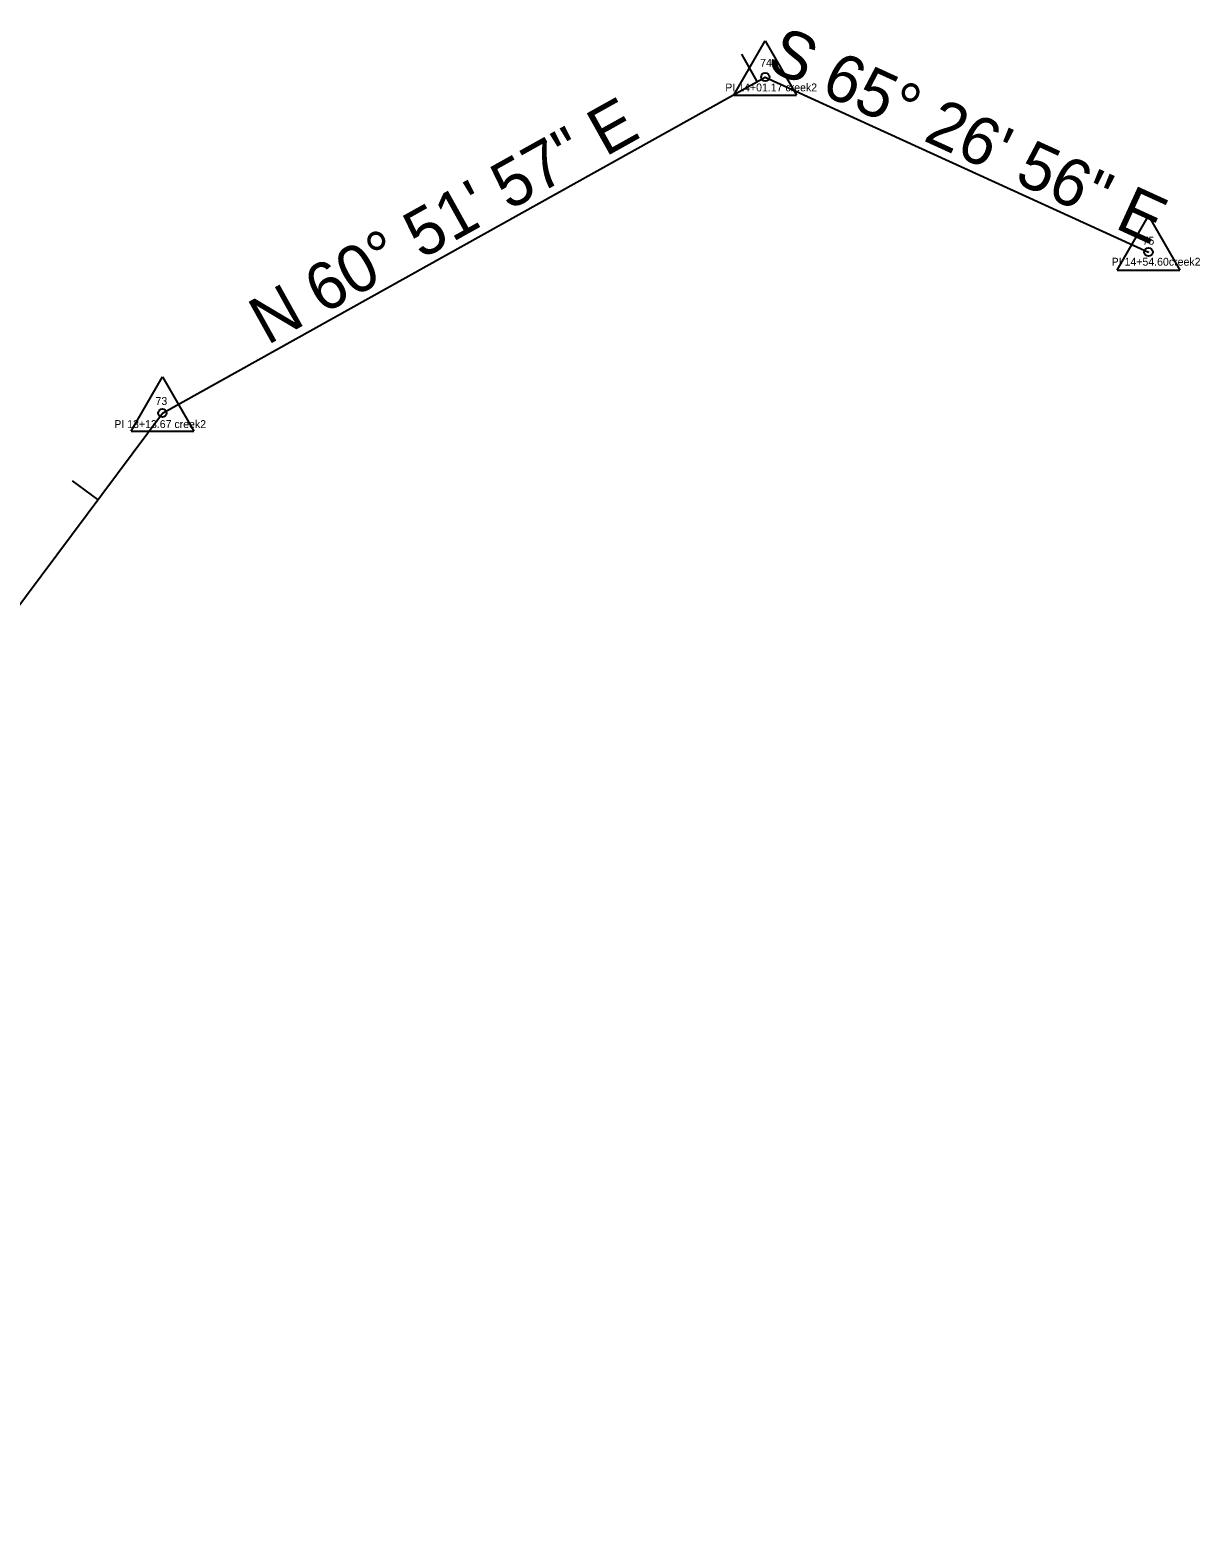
# Model space of a CAD drawing. Extents: x 1815672 to 1818258, y 1179223 to 1179901.
# Drawn here: x 1815904.3 to 1816052.7, y 1179317.3 to 1179507.4 of the extents above; entities that cross this region are included whole.
import ezdxf

# ---------------------------------------------------------------- set-up
doc = ezdxf.new("R2010")
doc.units = 0
for name, color, linetype in [('RD_EX_Misc', 7, 'Continuous'), ('RD_EX_Misc_txCode', 7, 'Continuous'), ('RD_HC_CL', 7, 'Continuous'), ('RD_HC_Data_Tic', 7, 'Continuous'), ('RD_SMD_Locator', 7, 'Continuous')]:
    doc.layers.add(name, color=color, linetype=linetype)

msp = doc.modelspace()

# ---------------------------------------------------------------- linework, layer by layer
at = {"layer": 'RD_EX_Misc'}
for p, q in [((1815993.57, 1179499.13), (1815997.54, 1179506.01)), ((1815997.54, 1179506.01), (1816001.51, 1179499.13)), ((1815993.57, 1179499.13), (1816001.51, 1179499.13)), ((1816042.16, 1179476.93), (1816046.13, 1179483.81)), ((1816046.13, 1179483.81), (1816050.1, 1179476.93)), ((1816042.16, 1179476.93), (1816050.1, 1179476.93)), ((1815917.14, 1179456.53), (1815921.11, 1179463.41)), ((1815921.11, 1179463.41), (1815925.08, 1179456.53)), ((1815917.14, 1179456.53), (1815925.08, 1179456.53))]:
    msp.add_line(p, q, dxfattribs=at)
for centre in [(1815997.54, 1179501.42), (1816046.13, 1179479.23), (1815921.11, 1179458.82)]:
    msp.add_circle(centre, 0.529, dxfattribs=at)
at = {"layer": 'RD_HC_CL'}
for p, q in [((1815921.11, 1179458.82), (1815997.54, 1179501.42)), ((1815997.54, 1179501.42), (1816046.13, 1179479.23)), ((1815815.49, 1179317.26), (1815921.11, 1179458.82))]:
    msp.add_line(p, q, dxfattribs=at)
at = {"layer": 'RD_HC_Data_Tic'}
for p, q in [((1815996.52, 1179500.85), (1815994.57, 1179504.34)), ((1815912.93, 1179447.86), (1815909.73, 1179450.26))]:
    msp.add_line(p, q, dxfattribs=at)
at = {"layer": 'RD_SMD_Locator'}
for centre in [(1815997.54, 1179501.42), (1816046.13, 1179479.23), (1815921.11, 1179458.82)]:
    msp.add_circle(centre, 0.001, dxfattribs=at)

# ---------------------------------------------------------------- texts
at = {"layer": 'RD_EX_Misc'}
for s, rotation, p in [('S 65%%d 26\' 56" E', 335.4488, (1815997.47, 1179502.55)), ('N 60%%d 51\' 57" E', 29.1341, (1815934.4, 1179467.37))]:
    msp.add_text(s, height=6, rotation=rotation, dxfattribs=at).set_placement(p)
at = {"layer": 'RD_EX_Misc_txCode'}
for s, p in [('74', (1815996.9, 1179502.72)), ('PI 14+01.17 creek2', (1815992.48, 1179499.6)), ('75', (1816045.38, 1179480.17)), ('PI 14+54.60creek2', (1816041.46, 1179477.51)), ('73', (1815920.24, 1179459.86)), ('PI 13+13.67 creek2', (1815915.02, 1179456.93))]:
    msp.add_text(s, height=1, dxfattribs=at).set_placement(p)

doc.saveas('drawing.dxf')
